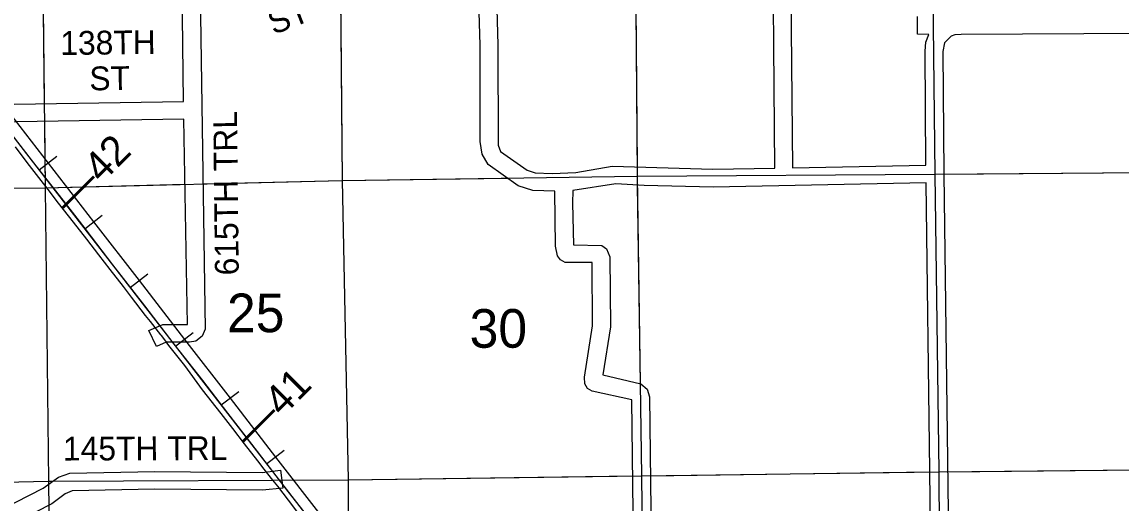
# Model space of a CAD drawing. Extents: x 10133 to 81668, y 5524 to 11018.
# Drawn here: x 15233.9 to 15696.2, y 9061 to 9263.3 of the extents above; entities that cross this region are included whole.
import ezdxf

# ---------------------------------------------------------------- set-up
doc = ezdxf.new("R2010")
doc.units = 0
doc.layers.add('Default', color=7, linetype='Continuous')

msp = doc.modelspace()

# ---------------------------------------------------------------- linework, layer by layer
at = {"layer": 'Default'}
for p, q in [((15241.17, 9201.08), (15248.57, 9206.83)), ((15260.28, 9176.37), (15267.69, 9182.11)), ((15279.4, 9151.67), (15286.77, 9157.46)), ((15298.53, 9126.95), (15305.93, 9132.72)), ((15317.66, 9102.27), (15325.08, 9107.99)), ((15336.78, 9077.52), (15344.2, 9083.26))]:
    msp.add_line(p, q, dxfattribs=at)
for points in [[(15308.74, 9284.89), (15310.88, 9134.18), (15309.62, 9131.25), (15307.07, 9129.14), (15304.36, 9128.64), (15294.54, 9128.72), (15290.44, 9126.84), (15287.3, 9133.64), (15293.09, 9136.14), (15303.47, 9136.14), (15302.03, 9222.4), (15222.5, 9221.13), (15218.75, 9219.37), (15215.57, 9226.16), (15221.63, 9228.62), (15301.85, 9229.9), (15299.87, 9396.97)], [(15367.42, 9320.74), (15368.57, 9196.71)], [(15456.96, 9199.66), (15466.93, 9200.03), (15482.16, 9202.68), (15524.57, 9201.39), (15550.57, 9201.82), (15549.56, 9322.22)], [(15491.64, 9321.53), (15492.63, 9202.21)], [(15491.64, 9321.53), (15492.66, 9198.43)], [(15557.06, 9322.26), (15557.46, 9260.1), (15558.07, 9201.93)], [(15616.48, 9324.14), (15617.93, 9199.35)], [(15242.24, 9319.19), (15243.29, 9228.96)], [(15242.24, 9319.19), (15243.7, 9193.61)], [(15367.68, 9292.6), (15368.57, 9196.71)], [(15433.12, 9289.05), (15434.07, 9253.7), (15434.21, 9211.54), (15435.18, 9208.89), (15446.33, 9200.93), (15449.81, 9199.94), (15456.96, 9199.66)], [(15492.22, 8951.09), (15490.41, 9104.45), (15473.77, 9108.14), (15471.8, 9109.25), (15470.64, 9111.18), (15470.48, 9113.9), (15473.91, 9135.49), (15473.79, 9162.12), (15462.42, 9162.16), (15460.37, 9163.28), (15459.09, 9164.93), (15458.38, 9168.99), (15458.06, 9192.17), (15448.78, 9192.51), (15442.68, 9194.36), (15430.04, 9203.41), (15427.44, 9207.69), (15426.61, 9213.07), (15426.57, 9253.6), (15425.66, 9286.07)], [(15558.07, 9201.93), (15614.14, 9203.17), (15613.8, 9251.01), (15614.16, 9254.86), (15615.33, 9258.11), (15610.56, 9258.16), (15610.63, 9265.66)], [(15732.2, 9258.65), (15629.03, 9258.06), (15626.32, 9257.97), (15624.7, 9257.4), (15621.91, 9254.5), (15621.3, 9250.87), (15621.67, 9199.39), (15623.64, 9046.33), (15623.85, 8984.02), (15669.93, 8984.23)], [(15225.77, 9228.6), (15244.84, 9203.95), (15264.01, 9179.26), (15283.12, 9154.54), (15302.23, 9129.83), (15321.41, 9105.13), (15340.51, 9080.39), (15359.67, 9055.74)], [(15225.4, 9221.29), (15238.22, 9204.83), (15251.04, 9188.35), (15257.88, 9179.52), (15260.7, 9175.87), (15271.96, 9161.15), (15285.49, 9143.93), (15297.79, 9127.9), (15309.8, 9112.51), (15320.32, 9098.87), (15332.78, 9082.73), (15345.78, 9065.94), (15358.62, 9049.46)], [(15243.37, 9221.46), (15243.7, 9193.61)], [(15668.79, 8651.87), (15660.38, 8659.96), (15653.04, 8667.42), (15647.71, 8673.19), (15640.22, 8682.58), (15632.91, 8692.86), (15619.33, 8714.58), (15595.31, 8753.24), (15589.23, 8764.01), (15584.53, 8773.92), (15580.77, 8783.66), (15576.82, 8798.44), (15574.18, 8809.77), (15568.57, 8832.34), (15562.14, 8845.7), (15555.95, 8854.72), (15549.63, 8861.86), (15543.4, 8867.64), (15508.98, 8900.29), (15441, 8963.76), (15433.45, 8970.54), (15385.03, 9016.02), (15376.46, 9026.55), (15227.85, 9218.32)], [(15351.66, 9054.81), (15345.95, 9062.23), (15341.48, 9068.06), (15339.47, 9070.59), (15335.81, 9075.21), (15333.1, 9078.72), (15327.52, 9085.97), (15322.55, 9092.35), (15317.65, 9098.64), (15309.89, 9108.69), (15302.33, 9118.8), (15295.71, 9127.34), (15294.01, 9129.62), (15292.55, 9131.5), (15292.28, 9131.81), (15287.91, 9137.36), (15285.9, 9139.91), (15279.95, 9147.65), (15276.53, 9152.03), (15271.04, 9159.18), (15266.2, 9165.41), (15261.15, 9172.03), (15255.54, 9179.19), (15249.28, 9187.14), (15244.97, 9192.81), (15236.12, 9204.25), (15231.16, 9210.78)], [(15617.93, 9199.35), (15742.15, 9200.28)], [(15621.68, 9199.38), (15738.43, 9200.25)], [(15243.7, 9193.61), (15368.57, 9196.71)], [(15310.05, 9195.26), (15368.57, 9196.71)], [(15368.57, 9196.71), (15492.66, 9198.43)], [(15368.57, 9196.71), (15438.09, 9197.67)], [(15368.57, 9196.71), (15371.17, 9070.8)], [(15368.57, 9196.71), (15371.17, 9070.8)], [(15601.74, 8952.34), (15616.32, 8952.63), (15616.45, 9013.81), (15615.81, 9074.58), (15614.22, 9195.67), (15524.59, 9193.89), (15495.56, 9194.51), (15483.71, 9195.21), (15465.56, 9192.41), (15465.48, 9187.08), (15465.87, 9169.58), (15477.78, 9169.26), (15479.82, 9167.86), (15481.16, 9164.51), (15481.41, 9135.14), (15478.27, 9114.92), (15494.17, 9111.14), (15496.84, 9108.9), (15497.91, 9105.66), (15499.71, 8951.15), (15601.74, 8952.34)], [(15492.66, 9198.43), (15617.93, 9199.35)], [(15492.66, 9198.43), (15494.56, 9072.46)], [(15617.93, 9199.35), (15619.56, 9074.16)], [(15118.18, 9192.67), (15243.7, 9193.61)], [(15118.18, 9192.67), (15243.7, 9193.61)], [(15243.7, 9193.61), (15302.55, 9195.07)], [(15243.7, 9193.61), (15245.03, 9070.19)], [(15243.7, 9193.61), (15245.03, 9070.19)], [(15492.71, 9194.68), (15493.98, 9111.2)], [(15619.56, 9074.16), (15743.98, 9075.39)], [(15623.31, 9074.2), (15743.98, 9075.39)], [(15213.92, 9052.55), (15242.75, 9067.24), (15249.19, 9071.95), (15253.99, 9073.61), (15289.72, 9074.31), (15334.99, 9073.93), (15342.7, 9074.79), (15343.67, 9067.35), (15335.13, 9066.44), (15289.75, 9066.81), (15254.98, 9066.16), (15252.03, 9064.89), (15246.38, 9060.68), (15217.94, 9046.21)], [(15245.03, 9070.19), (15371.17, 9070.8)], [(15343.24, 9070.67), (15371.17, 9070.8)], [(15371.17, 9070.8), (15494.56, 9072.46)], [(15371.17, 9070.8), (15490.79, 9072.41)], [(15371.17, 9070.8), (15371.34, 9012.49)], [(15371.17, 9070.8), (15371.52, 8945.85)], [(15494.56, 9072.46), (15619.56, 9074.16)], [(15494.56, 9072.46), (15495.95, 8947.37)], [(15498.28, 9072.51), (15615.81, 9074.11)], [(15619.56, 9074.16), (15620.24, 8948.93)], [(15119.9, 9067.44), (15245.03, 9070.19)], [(15119.9, 9067.44), (15245.03, 9070.19)], [(15245.03, 9070.19), (15246.63, 9070.2)], [(15245.03, 9070.19), (15245.04, 9068.98)], [(15245.03, 9070.19), (15246.45, 8945)]]:
    msp.add_lwpolyline(points, dxfattribs=at)

# ---------------------------------------------------------------- texts
for s, height, rotation, p in [('ST', 10, 21.2448, (15339.72, 9257.82)), ('138TH', 10, 0.6662, (15250.06, 9249.41)), ('ST', 10, 0.6662, (15262.29, 9234.55)), ('615TH TRL', 10, 90.6384, (15325.09, 9156.8)), ('‒‒42', 12.5, 45, (15254.3, 9181.95)), ('25', 16.25, 0.0256, (15320.13, 9132.86)), ('30', 16.25, 0.0262, (15422.2, 9126.33)), ('‒‒41', 12.5, 45, (15330.21, 9083.76)), ('145TH TRL', 10, 0.1726, (15251.16, 9078.91))]:
    msp.add_text(s, height=height, rotation=rotation, dxfattribs=at).set_placement(p)

doc.saveas('drawing.dxf')
